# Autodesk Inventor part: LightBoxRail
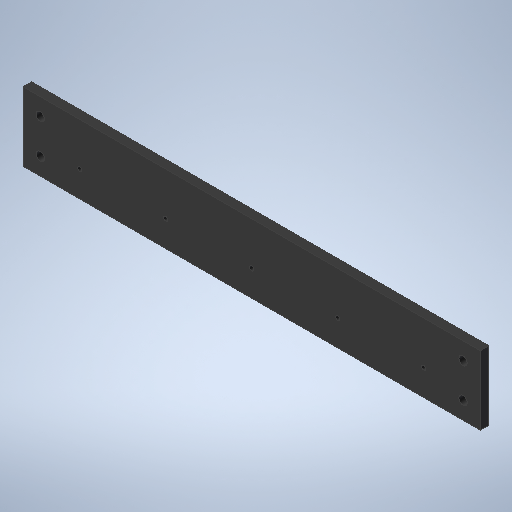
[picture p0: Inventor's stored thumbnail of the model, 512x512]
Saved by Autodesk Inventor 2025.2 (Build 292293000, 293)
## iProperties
Created: 2025-09
Part Number: LightBoxRail
Material: Generic
Document SubType Name: Modeling
Designer: tyler
Density: 1 g/cm^3
Appearance: Default
Author: tyler
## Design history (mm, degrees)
sketch "Sketch1"
  geometry: L1 (-168.783, 25.4)-(168.783, 25.4); L2 (168.783, 25.4)-(168.783, -25.4); L3 (168.783, -25.4)-(-168.783, -25.4); L4 (-168.783, -25.4)-(-168.783, 25.4); L5 (-168.783, 25.4)-(168.783, -25.4); L6 (168.783, 25.4)-(-168.783, -25.4); 1 further point
  constraints: 12 end point, 2 midpoint, 2 parallel, 1 horizontal, 1 perpendicular
  dimensions: "d0" = 337.566 distance of L2.end L3.end; "d1" = 50.8 distance of L1.end L2.end
extrude "Extrusion1" new body sketch "Sketch1" distance "d2" = 6.35; taper "d3" = 0 deg
sketch "Sketch2"
  geometry: L1 (-168.783, 25.4)-(-168.783, -25.4) reference; L2 (-168.783, 0)-(-168.783, -19.05); L3 (-168.783, 0)-(-168.783, 6.35); L4 (-168.783, 6.35)-(168.783, 6.35); L5 (168.783, -25.4)-(168.783, 25.4) reference; L6 (-168.783, -19.05)-(168.783, -19.05); L7 (0, 6.35)-(0, -19.05); L8 (0, -6.35)-(63.5, -6.35); L9 (63.5, -6.35)-(127, -6.35); L10 (0, -6.35)-(-63.5, -6.35); L11 (-63.5, -6.35)-(-127, -6.35); L12 (168.783, 25.4)-(156.083, 25.4); L13 (168.783, 25.4)-(-168.783, 25.4) reference; L14 (156.083, 25.4)-(156.083, 12.7); L15 (-168.783, 25.4)-(-156.083, 25.4); L16 (-156.083, 25.4)-(-156.083, 12.7); L17 (-168.783, 0)-(-156.083, 0); C1 r 1.587 at (-127, -6.35); C2 r 1.588 at (-63.5, -6.35); C3 r 1.587 at (0, -6.35); C4 r 1.587 at (63.5, -6.35); C5 r 1.588 at (127, -6.35); C6 r 3.175 at (-156.083, 12.7); C7 r 3.175 at (156.083, 12.7); C8 r 3.175 at (-156.083, -12.7); C9 r 3.175 at (156.083, -12.7); 1 further point
  constraints: 28 end point, 9 centre point, 8 point on line, 7 coincident, 4 midpoint, 4 perpendicular, 3 horizontal, 2 symmetric about line, 2 other
  dimensions: "d4" = 19.05 distance of L2.start L2.end; "d5" = 6.35 distance of L2.start L3.end; "d6" = 63.5 distance of L8.start L8.end; "d7" = 63.5 distance of L8.end L9.end; "d8" = 63.5 distance of L8.start L10.end; "d9" = 63.5 distance of L10.end L11.end; "d10" = 3.175 diameter of C1; "d11" = 3.175 diameter of C2; "d12" = 3.175 diameter of C3; "d13" = 3.175 diameter of C4; "d14" = 3.175 diameter of C5; "d15" = 12.7 distance of L5.end L12.end; "d16" = 12.7 distance of L12.end L14.end; "d17" = 12.7 distance of L1.start L15.end; "d18" = 12.7 distance of L15.end L16.end; "d19" = 6.35 diameter of C6; "d20" = 6.35 diameter of C7
extrude "Extrusion2" cut sketch "Sketch2" distance "d21" = 25.4; taper "d22" = 0 deg
body "Solid1"
